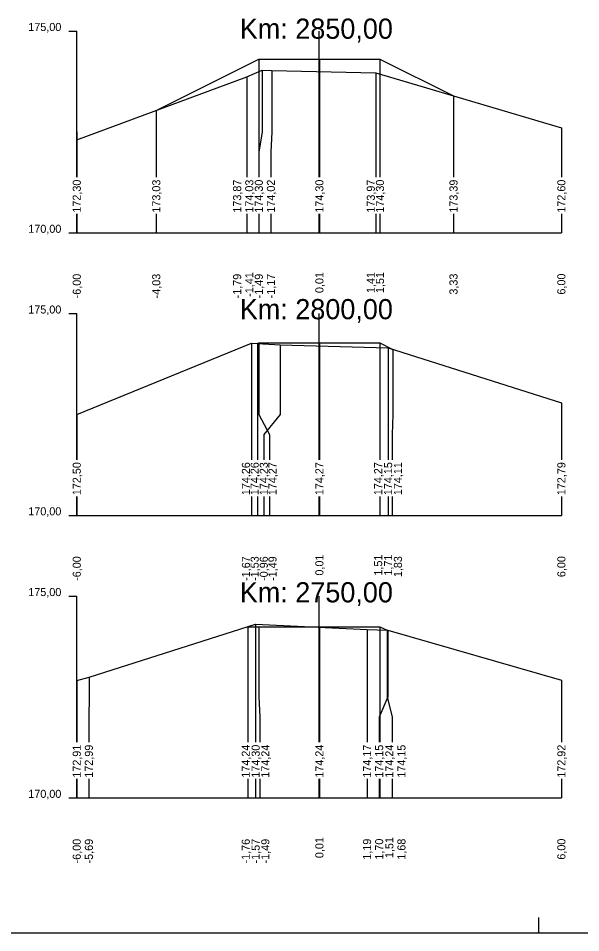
# Model space of a CAD drawing. Extents: x -614174 to -599765, y -1185887 to -1181080.
# Drawn here: x -601061.84 to -601047.91, y -1184533.61 to -1184510.95 of the extents above; entities that cross this region are included whole.
import ezdxf

# ---------------------------------------------------------------- set-up
doc = ezdxf.new("R2010")
doc.units = 0
for name, color, linetype in [('11', 7, 'Continuous'), ('16', 7, 'Continuous'), ('21', 7, 'Continuous'), ('28', 7, 'Continuous'), ('59', 7, 'Continuous'), ('8', 7, 'Continuous'), ('návrh', 7, 'Continuous')]:
    doc.layers.add(name, color=color, linetype=linetype)

msp = doc.modelspace()

# ---------------------------------------------------------------- linework, layer by layer
for points in [[(-601058.42, -1184513.235), (-601055.881, -1184511.966), (-601054.381, -1184511.966), (-601052.881, -1184511.966), (-601051.06, -1184512.876)], [(-601055.881, -1184511.966), (-601055.881, -1184511.966), (-601055.881, -1184511.966)], [(-601054.381, -1184511.966), (-601054.381, -1184511.966), (-601054.381, -1184511.966)], [(-601052.881, -1184511.966), (-601052.881, -1184511.966), (-601052.881, -1184511.966)], [(-601060.389, -1184513.969), (-601056.181, -1184512.401), (-601055.794, -1184512.243), (-601055.559, -1184512.25), (-601052.983, -1184512.303), (-601048.389, -1184513.672)], [(-601058.42, -1184513.235), (-601058.42, -1184513.235), (-601058.421, -1184513.235)], [(-601060.389, -1184520.773), (-601056.058, -1184519.007), (-601055.349, -1184519.041), (-601052.679, -1184519.12), (-601048.389, -1184520.483)], [(-601055.914, -1184519.014), (-601055.881, -1184518.997), (-601054.381, -1184518.997), (-601052.881, -1184518.997), (-601052.562, -1184519.157)], [(-601055.914, -1184519.014), (-601055.914, -1184519.014), (-601055.914, -1184519.014)], [(-601055.881, -1184518.997), (-601055.881, -1184518.997), (-601055.881, -1184518.997)], [(-601054.381, -1184518.997), (-601054.381, -1184518.997), (-601054.381, -1184518.997)], [(-601052.881, -1184518.997), (-601052.881, -1184518.997), (-601052.881, -1184518.997)], [(-601060.389, -1184527.365), (-601060.079, -1184527.279), (-601055.959, -1184525.968), (-601053.201, -1184526.101), (-601052.687, -1184526.118), (-601048.389, -1184527.351)], [(-601056.152, -1184526.029), (-601055.881, -1184526.029), (-601054.381, -1184526.029), (-601052.881, -1184526.029), (-601052.705, -1184526.117)], [(-601055.881, -1184526.029), (-601055.881, -1184526.029), (-601055.881, -1184526.029)], [(-601054.381, -1184526.029), (-601054.381, -1184526.029), (-601054.381, -1184526.029)], [(-601052.881, -1184526.029), (-601052.881, -1184526.029), (-601052.881, -1184526.029)]]:
    msp.add_lwpolyline(points)
at = {"layer": '11'}
for points in [[(-601055.881, -1184511.966), (-601055.881, -1184513.77), (-601055.881, -1184514.27), (-601055.881, -1184514.892)], [(-601054.381, -1184511.966), (-601054.381, -1184513.77), (-601054.381, -1184514.27), (-601054.381, -1184514.892)], [(-601052.881, -1184511.966), (-601052.881, -1184513.77), (-601052.881, -1184514.27), (-601052.881, -1184514.892)], [(-601055.794, -1184512.243), (-601055.794, -1184513.77), (-601055.881, -1184514.27), (-601055.881, -1184514.892)], [(-601055.559, -1184512.25), (-601055.559, -1184513.77), (-601055.581, -1184514.27), (-601055.581, -1184514.892)], [(-601056.181, -1184512.401), (-601056.181, -1184513.77), (-601056.181, -1184514.27), (-601056.181, -1184514.892)], [(-601052.983, -1184512.303), (-601052.983, -1184513.77), (-601052.983, -1184514.27), (-601052.983, -1184514.892)], [(-601051.06, -1184512.876), (-601051.06, -1184513.77), (-601051.06, -1184514.27), (-601051.06, -1184514.892)], [(-601058.42, -1184513.235), (-601058.42, -1184513.77), (-601058.42, -1184514.27), (-601058.42, -1184514.892)], [(-601060.389, -1184513.969), (-601060.389, -1184513.77), (-601060.389, -1184514.27), (-601060.389, -1184514.892)], [(-601048.389, -1184513.672), (-601048.389, -1184513.77), (-601048.389, -1184514.27), (-601048.389, -1184514.892)], [(-601060.389, -1184515.8), (-601060.389, -1184516.27)], [(-601058.42, -1184515.8), (-601058.42, -1184516.27)], [(-601056.181, -1184515.8), (-601056.181, -1184516.27)], [(-601055.881, -1184515.8), (-601055.881, -1184516.27)], [(-601055.881, -1184515.8), (-601055.881, -1184516.27)], [(-601055.581, -1184515.8), (-601055.581, -1184516.27)], [(-601054.381, -1184515.8), (-601054.381, -1184516.27)], [(-601052.983, -1184515.8), (-601052.983, -1184516.27)], [(-601052.881, -1184515.8), (-601052.881, -1184516.27)], [(-601051.06, -1184515.8), (-601051.06, -1184516.27)], [(-601048.389, -1184515.8), (-601048.389, -1184516.27)], [(-601056.058, -1184519.007), (-601056.058, -1184520.77), (-601056.058, -1184521.27), (-601056.058, -1184521.892)], [(-601055.914, -1184519.014), (-601055.914, -1184520.77), (-601055.914, -1184521.27), (-601055.914, -1184521.892)], [(-601055.881, -1184518.997), (-601055.881, -1184520.77), (-601055.614, -1184521.27), (-601055.614, -1184521.892)], [(-601055.349, -1184519.041), (-601055.349, -1184520.77), (-601055.758, -1184521.27), (-601055.758, -1184521.892)], [(-601054.381, -1184518.997), (-601054.381, -1184520.77), (-601054.381, -1184521.27), (-601054.381, -1184521.892)], [(-601052.881, -1184518.997), (-601052.881, -1184520.77), (-601052.881, -1184521.27), (-601052.881, -1184521.892)], [(-601052.679, -1184519.12), (-601052.679, -1184520.77), (-601052.679, -1184521.27), (-601052.679, -1184521.892)], [(-601052.562, -1184519.157), (-601052.562, -1184520.77), (-601052.581, -1184521.27), (-601052.581, -1184521.892)], [(-601048.389, -1184520.483), (-601048.389, -1184520.77), (-601048.389, -1184521.27), (-601048.389, -1184521.892)], [(-601060.389, -1184520.773), (-601060.389, -1184520.77), (-601060.389, -1184521.27), (-601060.389, -1184521.892)], [(-601060.389, -1184522.8), (-601060.389, -1184523.27)], [(-601056.058, -1184522.8), (-601056.058, -1184523.27)], [(-601055.914, -1184522.8), (-601055.914, -1184523.27)], [(-601055.758, -1184522.8), (-601055.758, -1184523.27)], [(-601055.614, -1184522.8), (-601055.614, -1184523.27)], [(-601054.381, -1184522.8), (-601054.381, -1184523.27)], [(-601052.881, -1184522.8), (-601052.881, -1184523.27)], [(-601052.679, -1184522.8), (-601052.679, -1184523.27)], [(-601052.581, -1184522.8), (-601052.581, -1184523.27)], [(-601048.389, -1184522.8), (-601048.389, -1184523.27)], [(-601056.152, -1184526.029), (-601056.152, -1184527.77), (-601056.152, -1184528.27), (-601056.152, -1184528.892)], [(-601055.959, -1184525.968), (-601055.959, -1184527.77), (-601055.959, -1184528.27), (-601055.959, -1184528.892)], [(-601055.881, -1184526.029), (-601055.881, -1184527.77), (-601055.852, -1184528.27), (-601055.852, -1184528.892)], [(-601054.381, -1184526.029), (-601054.381, -1184527.77), (-601054.381, -1184528.27), (-601054.381, -1184528.892)], [(-601053.201, -1184526.101), (-601053.201, -1184527.77), (-601053.201, -1184528.27), (-601053.201, -1184528.892)], [(-601052.881, -1184526.029), (-601052.881, -1184527.77), (-601052.881, -1184528.27), (-601052.881, -1184528.892)], [(-601052.687, -1184526.118), (-601052.687, -1184527.77), (-601052.901, -1184528.27), (-601052.901, -1184528.892)], [(-601052.705, -1184526.117), (-601052.705, -1184527.77), (-601052.581, -1184528.27), (-601052.581, -1184528.892)], [(-601060.389, -1184527.365), (-601060.389, -1184527.77), (-601060.389, -1184528.27), (-601060.389, -1184528.892)], [(-601060.079, -1184527.279), (-601060.079, -1184527.77), (-601060.089, -1184528.27), (-601060.089, -1184528.892)], [(-601048.389, -1184527.351), (-601048.389, -1184527.77), (-601048.389, -1184528.27), (-601048.389, -1184528.892)], [(-601060.389, -1184529.8), (-601060.389, -1184530.27)], [(-601060.089, -1184529.8), (-601060.089, -1184530.27)], [(-601056.152, -1184529.8), (-601056.152, -1184530.27)], [(-601055.959, -1184529.8), (-601055.959, -1184530.27)], [(-601055.852, -1184529.8), (-601055.852, -1184530.27)], [(-601054.381, -1184529.8), (-601054.381, -1184530.27)], [(-601053.201, -1184529.8), (-601053.201, -1184530.27)], [(-601052.901, -1184529.8), (-601052.901, -1184530.27)], [(-601052.881, -1184529.8), (-601052.881, -1184530.27)], [(-601052.581, -1184529.8), (-601052.581, -1184530.27)], [(-601048.389, -1184529.8), (-601048.389, -1184530.27)]]:
    msp.add_lwpolyline(points, dxfattribs=at)
at = {"layer": '16'}
for p, q in [((-601060.389, -1184516.27), (-601048.389, -1184516.27)), ((-601060.389, -1184523.27), (-601048.389, -1184523.27)), ((-601060.389, -1184530.27), (-601048.389, -1184530.27))]:
    msp.add_line(p, q, dxfattribs=at)
for points in [[(-601051.06, -1184512.876), (-601051.06, -1184512.876), (-601051.06, -1184512.876)], [(-601052.562, -1184519.157), (-601052.562, -1184519.157), (-601052.562, -1184519.157)], [(-601052.705, -1184526.117), (-601052.705, -1184526.117), (-601052.705, -1184526.117)]]:
    msp.add_lwpolyline(points, dxfattribs=at)
at = {"layer": '21'}
for p, q in [((-601060.589, -1184511.27), (-601060.389, -1184511.27)), ((-601060.589, -1184516.27), (-601060.389, -1184516.27)), ((-601060.589, -1184518.27), (-601060.389, -1184518.27)), ((-601060.589, -1184523.27), (-601060.389, -1184523.27)), ((-601060.589, -1184525.27), (-601060.389, -1184525.27)), ((-601060.589, -1184530.27), (-601060.389, -1184530.27))]:
    msp.add_line(p, q, dxfattribs=at)
at = {"layer": '28'}
for p, q in [((-601054.389, -1184514.892), (-601054.389, -1184511.27)), ((-601054.389, -1184516.27), (-601054.389, -1184515.8)), ((-601054.389, -1184521.892), (-601054.389, -1184518.27)), ((-601054.389, -1184523.27), (-601054.389, -1184522.8)), ((-601054.389, -1184528.892), (-601054.389, -1184525.27)), ((-601054.389, -1184530.27), (-601054.389, -1184529.8))]:
    msp.add_line(p, q, dxfattribs=at)
at = {"layer": '8'}
for p, q in [((-601060.389, -1184514.892), (-601060.389, -1184511.27)), ((-601060.389, -1184516.27), (-601060.389, -1184515.8)), ((-601060.389, -1184521.892), (-601060.389, -1184518.27)), ((-601060.389, -1184523.27), (-601060.389, -1184522.8)), ((-601060.389, -1184528.892), (-601060.389, -1184525.27)), ((-601060.389, -1184530.27), (-601060.389, -1184529.8))]:
    msp.add_line(p, q, dxfattribs=at)
at = {"layer": 'návrh'}
for p, q in [((-601048.944, -1184533.61), (-601048.944, -1184533.23)), ((-601069.944, -1184533.61), (-601048.944, -1184533.61)), ((-601048.944, -1184533.61), (-601027.944, -1184533.61))]:
    msp.add_line(p, q, dxfattribs=at)

# ---------------------------------------------------------------- texts
msp.add_text('+', height=0.001).set_placement((-601056.152, -1184526.03))
at = {"layer": '16'}
for s, p in [('172,30', (-601060.289, -1184515.77)), ('173,03', (-601058.32, -1184515.77)), ('173,87', (-601056.317, -1184515.77)), ('174,03', (-601056.017, -1184515.77)), ('174,30', (-601055.781, -1184515.77)), ('174,02', (-601055.481, -1184515.77)), ('174,30', (-601054.281, -1184515.77)), ('173,97', (-601053.008, -1184515.77)), ('174,30', (-601052.781, -1184515.77)), ('173,39', (-601050.96, -1184515.77)), ('172,60', (-601048.289, -1184515.77)), ('172,50', (-601060.289, -1184522.77)), ('174,26', (-601056.1, -1184522.77)), ('174,26', (-601055.884, -1184522.77)), ('174,23', (-601055.658, -1184522.77)), ('174,27', (-601055.442, -1184522.77)), ('174,27', (-601054.281, -1184522.77)), ('174,27', (-601052.826, -1184522.77)), ('174,15', (-601052.579, -1184522.77)), ('174,11', (-601052.336, -1184522.77)), ('172,79', (-601048.289, -1184522.77)), ('172,91', (-601060.289, -1184529.77)), ('172,99', (-601059.989, -1184529.77)), ('174,24', (-601056.104, -1184529.77)), ('174,30', (-601055.859, -1184529.77)), ('174,24', (-601055.62, -1184529.77)), ('174,24', (-601054.281, -1184529.77)), ('174,17', (-601053.101, -1184529.77)), ('174,15', (-601052.801, -1184529.77)), ('174,24', (-601052.549, -1184529.77)), ('174,15', (-601052.249, -1184529.77)), ('172,92', (-601048.289, -1184529.77))]:
    msp.add_text(s, height=0.2, rotation=90, dxfattribs=at).set_placement(p)
at = {"layer": '21'}
for s, p in [('175,00', (-601061.589, -1184511.27)), ('170,00', (-601061.589, -1184516.27)), ('175,00', (-601061.589, -1184518.27)), ('170,00', (-601061.589, -1184523.27)), ('175,00', (-601061.589, -1184525.27)), ('170,00', (-601061.589, -1184530.27))]:
    msp.add_text(s, height=0.2, dxfattribs=at).set_placement(p)
at = {"layer": '28'}
for s, p in [('Km: 2850,00', (-601056.352, -1184511.462)), ('Km: 2800,00', (-601056.352, -1184518.411)), ('Km: 2750,00', (-601056.352, -1184525.426))]:
    msp.add_text(s, height=0.5, dxfattribs=at).set_placement(p)
at = {"layer": '59'}
for s, p in [('-1,41', (-601056.017, -1184517.855)), ('0,01', (-601054.281, -1184517.762)), ('1,41', (-601053.008, -1184517.762)), ('1,51', (-601052.781, -1184517.762)), ('-6,00', (-601060.289, -1184517.893)), ('-4,03', (-601058.32, -1184517.894)), ('-1,79', (-601056.317, -1184517.894)), ('-1,49', (-601055.781, -1184517.894)), ('-1,17', (-601055.481, -1184517.894)), ('3,33', (-601050.96, -1184517.801)), ('6,00', (-601048.289, -1184517.8)), ('-6,00', (-601060.289, -1184524.893)), ('-1,67', (-601056.1, -1184524.894)), ('-1,53', (-601055.884, -1184524.894)), ('-0,96', (-601055.658, -1184524.894)), ('-1,49', (-601055.442, -1184524.894)), ('0,01', (-601054.281, -1184524.762)), ('1,51', (-601052.826, -1184524.762)), ('1,71', (-601052.579, -1184524.762)), ('1,83', (-601052.336, -1184524.801)), ('6,00', (-601048.289, -1184524.8)), ('-6,00', (-601060.289, -1184531.893)), ('-5,69', (-601059.989, -1184531.894)), ('-1,76', (-601056.104, -1184531.894)), ('-1,57', (-601055.859, -1184531.894)), ('-1,49', (-601055.62, -1184531.894)), ('0,01', (-601054.281, -1184531.762)), ('1,19', (-601053.101, -1184531.801)), ('1,70', (-601052.801, -1184531.8)), ('1,51', (-601052.549, -1184531.762)), ('1,68', (-601052.249, -1184531.801)), ('6,00', (-601048.289, -1184531.8))]:
    msp.add_text(s, height=0.2, rotation=90, dxfattribs=at).set_placement(p)

doc.saveas('drawing.dxf')
